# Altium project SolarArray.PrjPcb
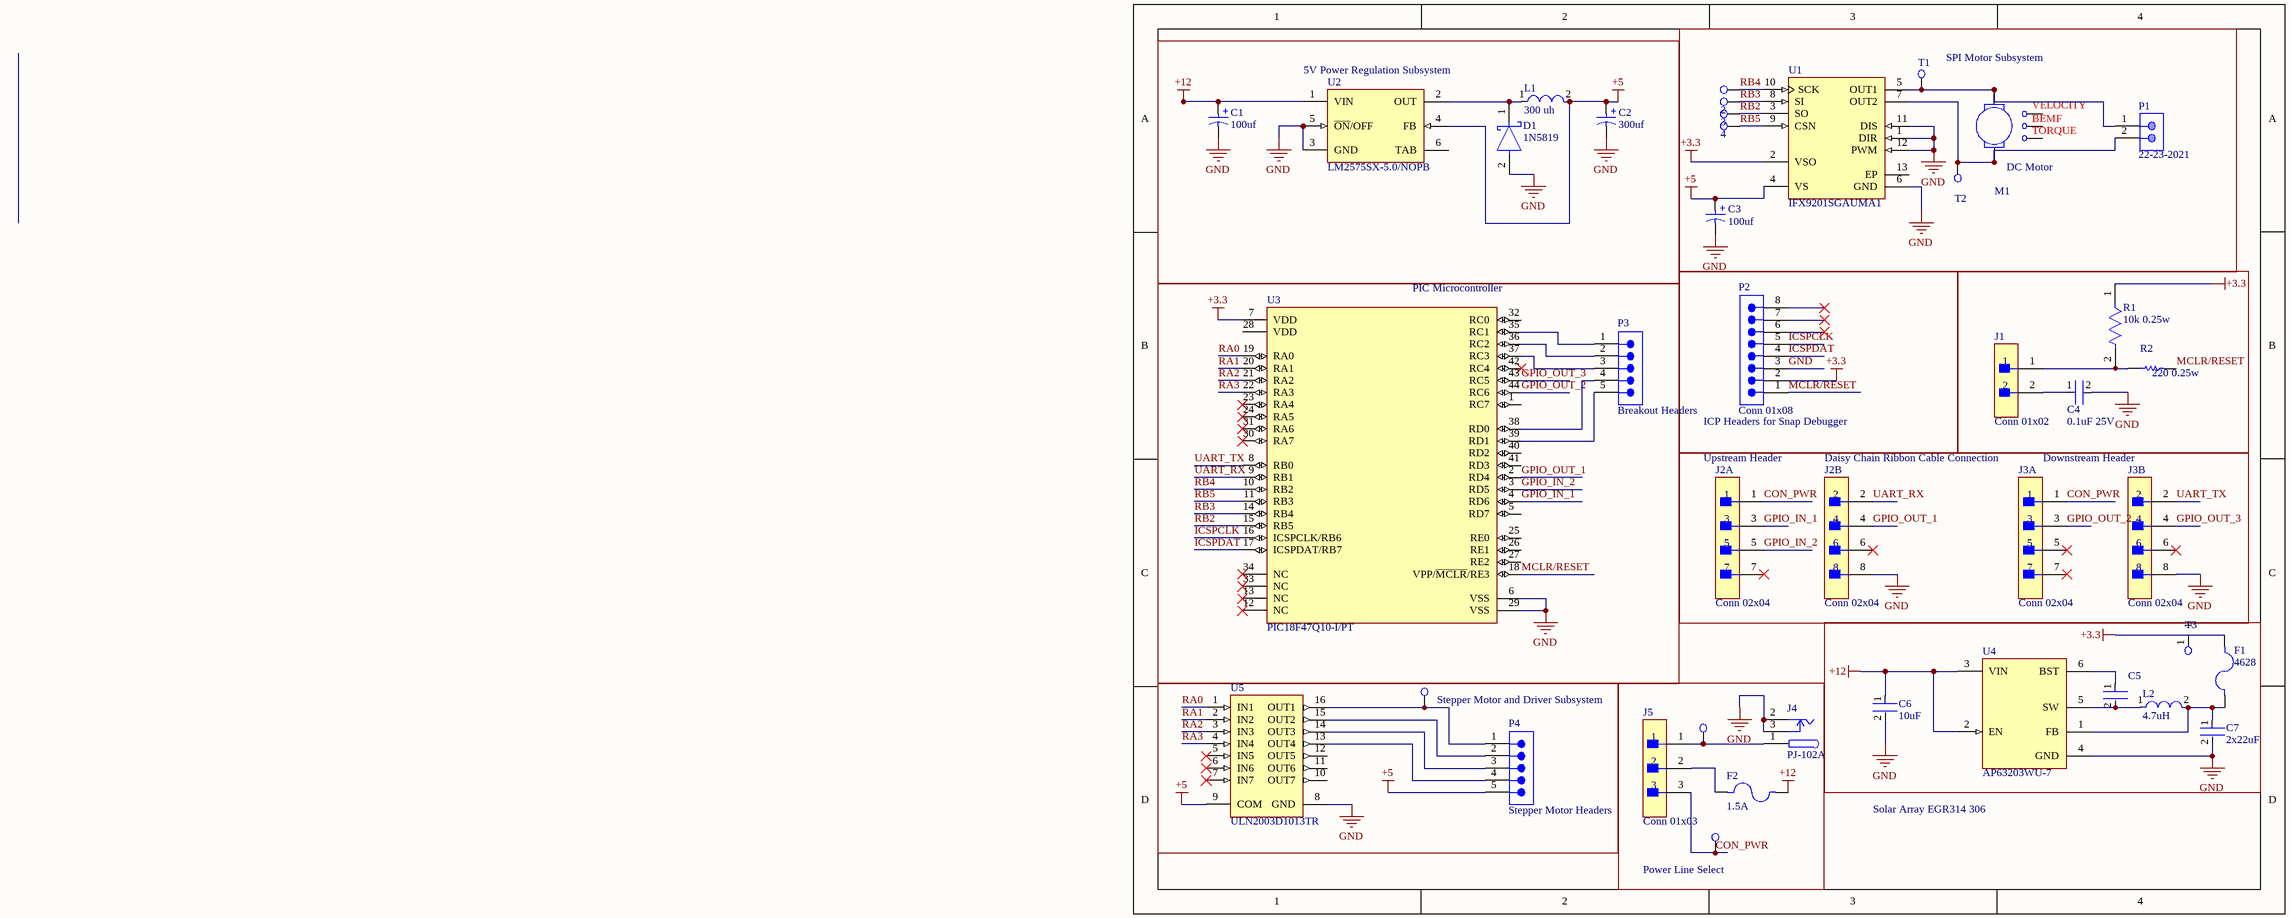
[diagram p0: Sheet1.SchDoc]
1 sheet, 39 parts. Net scope: global (net labels, ports and power ports of the same name join across sheets).
Board file: PCB1.PcbDoc

## Sheet Sheet1.SchDoc: Solar Array EGR314 306
size A; SheetNumber: 1; SheetTotal: 1

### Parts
1  Test point  [Test point-Footprint-1]  (value not drawn)
2  Test point  [Test point-Footprint-1]  (value not drawn)
3  Test point  [Test point-Footprint-1]  (value not drawn)
4  Test point  [Test point-Footprint-1]  (value not drawn)
C1  100uf  [WCAP-AS5H_D4H5.5]
C2  300uf  [WCAP-AS5H_D4H5.5]
C3  100uf  [WCAP-AS5H_D4H5.5]
C4  0.1uF 25V  [FP-C1206C-EB-MFG]
C5  (no value)  [FP-1206-L_3_2_0_2-W_1_6_0-IPC_B]
C6  10uF  [FP-1206-L_3_2_0_2-W_1_6_0-IPC_B]
C7  2x22uF  [FP-C3216-160-0_2-MFG]
D1  1N5819  [FP-SOD-123-MFG]
F1  4628  [FUSE_4628]
F2  1.5A  [FUSE_4628]
J1  Conn 01x02  [90120-0762-Footprint-1]
J2  Conn 02x04  [FP-0702460801-MFG]  (parts A,B of 2)
J3  Conn 02x04  [FP-0702460801-MFG]  (parts A,B of 2)
J4  PJ-102A  [FP-PJ-102A-MFG]
J5  Conn 01x03  [FP-90120-0123-MFG]
L1  300 uh  [FP-IHLP-2525EZ-FP_2_413x3-MFG]
L2  4.7uH  [FP-IHLP-2525EZ-FP_2_413x3-MFG]
M1  DC Motor
P1  22-23-2021  [MOLX-22-23-2021_V]
P2  Conn 01x08  [61300811121]
P3  Breakout Headers  [61300511121]
P4  Stepper Motor Headers  [61300511121]
R1  10k 0.25w  [FP-CR1206-IPC_C]
R2  220 0.25w  [RESC3216X60X45NL10T20]
T1  Test point  [Test point-Footprint-1]  (value not drawn)
T2  Test point  [Test point-Footprint-1]  (value not drawn)
T3  (no value)  [Test point-Footprint-1]
T4  Test point  [Test point-Footprint-1]  (value not drawn)
T5  Test point  [Test point-Footprint-1]  (value not drawn)
T6  Test point  [Test point-Footprint-1]  (value not drawn)
U1  IFX9201SGAUMA1  [INF-PG-DSO-12-17_L]
U2  LM2575SX-5.0/NOPB  [KTT0005B_L]
U3  PIC18F47Q10-I/PT  [FP-C04-076-IPC_A]
U4  AP63203WU-7  [FP-TSOT26-MFG]
U5  ULN2003D1013TR  [STM-SO-16_M]

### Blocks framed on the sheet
5V Power Regulation Subsystem: C1 C2 D1 L1 U2
SPI Motor Subsystem: 1-4 C3 M1 P1 T1 T2 U1
PIC Microcontroller: P3 U3
ICP Headers for Snap Debugger: P2
Stepper Motor and Driver Subsystem: P4 T4 U5
Power Line Select: F2 J4 J5 T5 T6

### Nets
+3.3: F1.2 P2.2 R1.1 U1.2(VSO) U3.7(VDD)
+5: C2.1(P) C3.1(P) L1.2 P4.5 U1.4(VS) U2.4(FB) U5.9(COM)
+12: C1.1(P) C6.1 F2.2 U2.1(VIN) U4.2(EN) U4.3(VIN)
GND: C1.2(N) C2.2(N) C3.2(N) C4.2 C6.2 C7.2 D1.2(A) J2.8 J3.8 J4.2 J4.3 P2.3 U1.1(DIR) U1.6(GND) U1.11(DIS) U1.12(PWM) U2.3(GND) U2.5(~{ON}/OFF) U3.6(VSS) U3.29(VSS) U4.4(GND) U5.8(GND)
CON_PWR: J2.1 J3.1 J5.3 T6.1
GPIO_IN_1: J2.3 U3.4(RD6)
GPIO_IN_2: J2.5 U3.3(RD5)
GPIO_OUT_1: J2.4 U3.2(RD4)
GPIO_OUT_2: J3.3 U3.44(RC6)
GPIO_OUT_3: J3.4 U3.43(RC5)
ICSPCLK: P2.5 U3.16(ICSPCLK/RB6)
ICSPDAT: P2.4 U3.17(ICSPDAT/RB7)
MCLR/RESET: P2.1 R2.2 U3.18(VPP/~{MCLR}/RE3)
RA0: U3.19(RA0) U5.1(IN1)
RA1: U3.20(RA1) U5.2(IN2)
RA2: U3.21(RA2) U5.3(IN3)
RA3: U3.22(RA3) U5.4(IN4)
RB2: 3.1 U1.3(SO) U3.15(RB5)
RB3: 2.1 U1.8(SI) U3.14(RB4)
RB4: 1.1 U1.10(SCK) U3.10(RB2)
RB5: 4.1 U1.9(CSN) U3.11(RB3)
UART_RX: J2.2 U3.9(RB1)
UART_TX: J3.2 U3.8(RB0)
NetC4_1: C4.1 J1.2
NetC5_1: C5.1 U4.6(BST)
NetC5_2: C5.2 L2.1 U4.5(SW)
NetC7_1: C7.1 F1.1 L2.2 U4.1(FB)
NetD1_1: D1.1(C) L1.1 U2.2(OUT)
NetF2_1: F2.1 J5.2
NetJ1_1: J1.1 R1.2 R2.1
NetJ4_1: J4.1 J5.1 T5.1
NetM1_1: M1.1 P1.1 T1.1 U1.5(OUT1)
NetM1_2: M1.2 P1.2 T2.1 U1.7(OUT2)
NetP3_1: P3.1 U3.35(RC1)
NetP3_2: P3.2 U3.36(RC2)
NetP3_3: P3.3 U3.37(RC3)
NetP3_4: P3.4 U3.38(RD0)
NetP3_5: P3.5 U3.39(RD1)
NetP4_1: P4.1 T4.1 U5.16(OUT1)
NetP4_2: P4.2 U5.15(OUT2)
NetP4_3: P4.3 U5.14(OUT3)
NetP4_4: P4.4 U5.13(OUT4)

Not connected (* = marked no-connect by the designer): J2 6* 7*; J3 5* 6* 7*; M1 3 4 5; P2 6* 7* 8*; T3 1; U1 13(EP); U2 6(TAB); U3 1(RC7) 5(RD7) 12(NC)* 13(NC)* 23(RA4)* 24(RA5)* 25(RE0) 26(RE1) 27(RE2) 28(VDD) 30(RA7)* 31(RA6)* 32(RC0) 33(NC)* 34(NC)* 40(RD2) 41(RD3) 42(RC4)*; U5 5(IN5)* 6(IN6)* 7(IN7)* 10(OUT7) 11(OUT6) 12(OUT5)

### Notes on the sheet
- (near J2) Upstream Header
- Daisy Chain Ribbon Cable Connection
- (near J3) Downstream Header

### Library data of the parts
1-4 T1 T2 T4-T6 = CMP-00030-4: tht test point
C1-C3 = CMP-00009-1: WCAP-AS5H Aluminum Electrolytic Capacitors
C4 = CMP-00015-1: Ceramic Capacitor, Multilayer, Ceramic, 25V, 10% +Tol, 10% -Tol, X7R, 15% TC, 0.1uF, Surface Mount, 1206; Multilayer: Yes; Value: 100nF
C5 C6 = CMP-00010-1: Ceramic Capacitor, Multilayer, Ceramic, 100V, 10% +Tol, 10% -Tol, X7R, 15% TC, 0.1uF, Surface Mount, 1206; Value: 100nF; Multilayer: Yes; Reference Standard: AEC-Q200
C7 = CMP-00013-1: Ceramic Capacitor, Multilayer, Ceramic, 35V, 20% +Tol, 20% -Tol, X5R, 15% TC, 22uF, Surface Mount, 1206; Multilayer: Yes
D1 = CMP-00040-1: Rectifier Diode, Schottky, 1 Phase, 1 Element, 0.5A, 60V V(RRM), Silicon; Forward Voltage: 660mV; Additional Feature: FREE WHEELING DIODE; Package Body Material: Plastic; Number of Elements: 1; Max Output current: 500mA; Time @ Peak Reflow Temperature-Max (s): 30s; Qualification Status: Not Qualified; Non-rep Pk Forward Current-Max: 5.5A
F1 F2 = CMP-006-000000-1: 5mm Slim Line Fuse holder; MF: Keystone
J1 = CMP-00026-1: Board Connector, 2 Contact(s), 1 Row(s), Male, Straight, 0.1 inch Pitch, Solder Terminal, Locking, Black Insulator, Receptacle; Number Of PCB Rows: 1; Dielectric Withstanding Voltage (DC): 1kV; Number of Contacts: 2; Body Length: 2.2inch; Reliability: COMMERCIAL; Option: General Purpose; MIL Conformance: No; Body Depth: 0.98inch; PCB Contact Pattern: RECTANGULAR; Insulation Resistance: 5GR; Contact Resistance: 20mR; Rated Current (Signal): 3A; Contact Style: SQ PIN-SKT; Plating Thickness: 15uin; Mating Information: MULTIPLE MATING PARTS AVAILABLE; Reference Standard: UL
J2 J3 = CMP-00034-1: Board Connector, 8 Contact(s), 2 Row(s), Male, Straight, 0.1 inch Pitch, Solder Terminal, Guide Slot, Black Insulator, Receptacle; Manufacturer Series: 70246; Filter Feature: No; Number Of PCB Rows: 2; Body Breadth: 0.35inch; PCB Contact Pattern: RECTANGULAR; Rated Current (Signal): 2.5A; Body Depth: 0.365inch; Dielectric Withstanding Voltage (AC): 900V; Reference Standard: UL; Contact Style: SQ PIN-SKT; Insulation Resistance: 12GR; Polarization Key: POLARIZED HOUSING; Option: General Purpose; Mounting Option 2: LOCKING; Reliability: COMMERCIAL; Plating Thickness: 15uin; Number of Contacts: 8; Additional Feature: SHROUDED; PCB Contact Row Spacing: 2.54mm; Number Of Connectors: 1; Body Length: 0.7inch
J4 = CMP-00031-1: 2.0 x 6.5 mm, 2.5 A, Horizontal, Through Hole, Tapered Pins, Dc Power Jack Connector
J5 = CMP-00025-1: Board Connector, 3 Contact(s), 1 Row(s), Male, Straight, 0.1 inch Pitch, Solder Terminal, Black Insulator, Receptacle; Body Depth: 0.098inch; Withdrawl Force-Min: 0.1946N; Plating Thickness: 160uin; Contact Resistance: 20mR; Body Length: 0.3inch; Filter Feature: No; Number Of PCB Rows: 1; Contact Style: SQ PIN-SKT; Mating Information: MULTIPLE MATING PARTS AVAILABLE; Reference Standard: UL; Insulation Resistance: 5GR; Dielectric Withstanding Voltage (DC): 350V; Reliability: COMMERCIAL; Contact Pattern: RECTANGULAR; Rated Current (Signal): 3A; Option: General Purpose; Number of Contacts: 3; Insertion Force-Max: 3.0024N
L1 L2 = CMP-00011-1: General Purpose Inductor, 4.7uH, 20%, 1 Element, Composite-Core, SMD, 2525; Test Frequency: 100kHz; Channels: 1; Package Width: 6.47mm; Max Current Rating: 6.5A; Inductor Application: HIGH CURRENT INDUCTOR; Shielding: Shielded; DC Resistance (DCR): 30.3mR; Core Material: Ferrite; Shape/Size Description: RECTANGULAR PACKAGE; Package Length: 6.86mm; Package Height: 5mm; Case/Size Code: 2726
M1 = DC Motor: LA: 1.5M; RA: 0.5; KE: 0.05; JM: 250U; BM: 0.1M; TL: 0; SimulationGenericComponent: True
P1 = CMP-1704-00001-3: Male Header, Pitch 2.54 mm, 1 x 2 Position, Height 10.67 mm, Tail Length 3.56 mm, 0 to 75 degC, RoHS, Bulk
P2 = CMP-00017-1: Board Connector, 8 Contact(s), 1 Row(s), Male, Straight, 0.1 inch Pitch, Solder Terminal, Locking, Black Insulator, Plug; Manufacturer Series: 613; Insulation Resistance: 1GR; Number of Contacts: 8; Dielectric Withstanding Voltage (AC): 500V; Contact Resistance: 20mR; Rated Current (Signal): 3A; Reference Standard: UL; PCB Contact Pattern: RECTANGULAR; Reliability: COMMERCIAL; Number Of Connectors: 1; Body Length: 0.8inch; Contact Style: SQ PIN-SKT
P3 P4 = CMP-1502-01068-3: NexarPartId: 32855526; Connector Type: Male Pin; Gender: Male; Contact Resistance: 20mΩ; Pitch: 2.54mm; Operating Supply Voltage: 250V; Current Rating: 3A; Number of Contacts: 5
R1 = CMP-00022-1: Fixed Resistor, Metal Glaze/thick Film, 0.25W, 10000ohm, 200V, 5% +/-Tol, 200ppm/Cel, Surface Mount, 1206; Package Width: 1.6mm; Package Height: 0.6mm; Power: 250mW; Value: 10kR; Temperature Coefficient (ppm/Cel): 200; Package Length: 3.2mm; Rated Temperature: 70°C
R2 = CMP-00024-1: Fixed Resistor, Metal Glaze/thick Film, 0.25W, 220ohm, 200V, 1% +/-Tol, 100ppm/Cel, Surface Mount, 1206; Value: 220R; Temperature Coefficient (ppm/Cel): 100; Additional Feature: RATED AC VOLTAGE (V): 200; Rated Temperature: 70°C; Reference Standard: AEC-Q200; Power: 250mW; Package Length: 3.2mm; Package Width: 1.6mm; Package Height: 0.55mm
T3 = CMP-00030-3: tht test point
U1 = CMP-1645-00001-1: 6 A H-Bridge with SPI, 0.1 Ohm, -40 to 125 degC, 12-Pin PG-DSO-12-17, RoHS, Tape and Reel; RDS(on): 0.1 Ohm
U2 = CMP-0069-00083-3: SIMPLE SWITCHER® 1A Step-Down Voltage Regulator, 5-pin TO-263, Pb-Free; Manufacturer: Texas Instruments; PackageTopMarking: NSUZXYTTE#*LM2575S*-5.0 P+; PowerWise: N
U3 = CMP-00000-1: RISC Microcontroller, 8-Bit, FLASH, PIC18 CPU, 64MHz, CMOS, PQFP44
U4 = CMP-00004-1: Switching Regulator
U5 = CMP-2000-05374-1: Seven NPN Darlington Array Transistor, 50 V, 500 mA, -40 to 85 degC, 8-Pin SOIC, RoHS, Tape and Reel; Manufacturer: STMicroelectronics; Collector Emitter Voltage V(br)ceo: 50V; SVHC: NoSVHC(17-Dec-2015); DC Current Gain hFE: 1000hFE; DC Collector Current: 500mA; No. of Pins: 16Pins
